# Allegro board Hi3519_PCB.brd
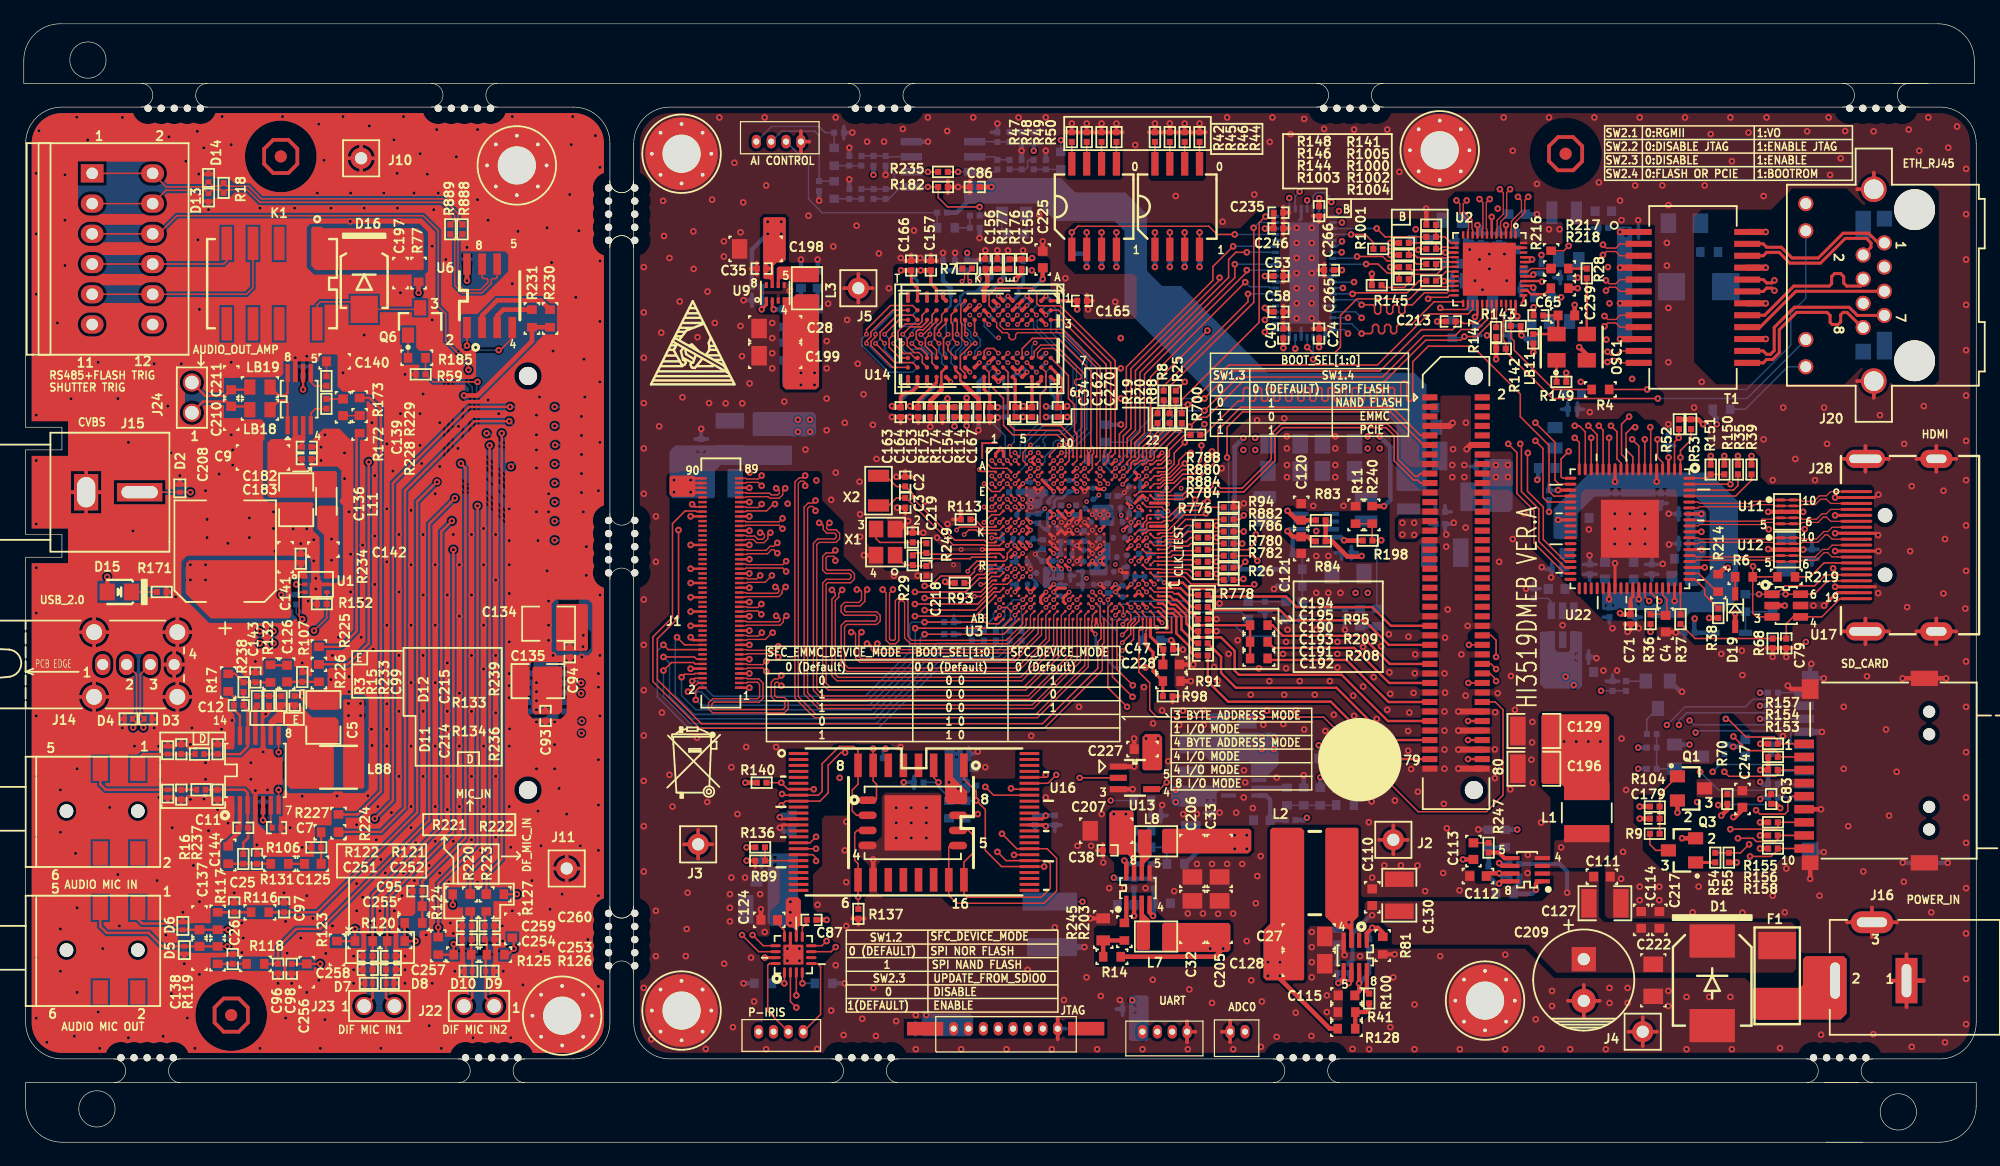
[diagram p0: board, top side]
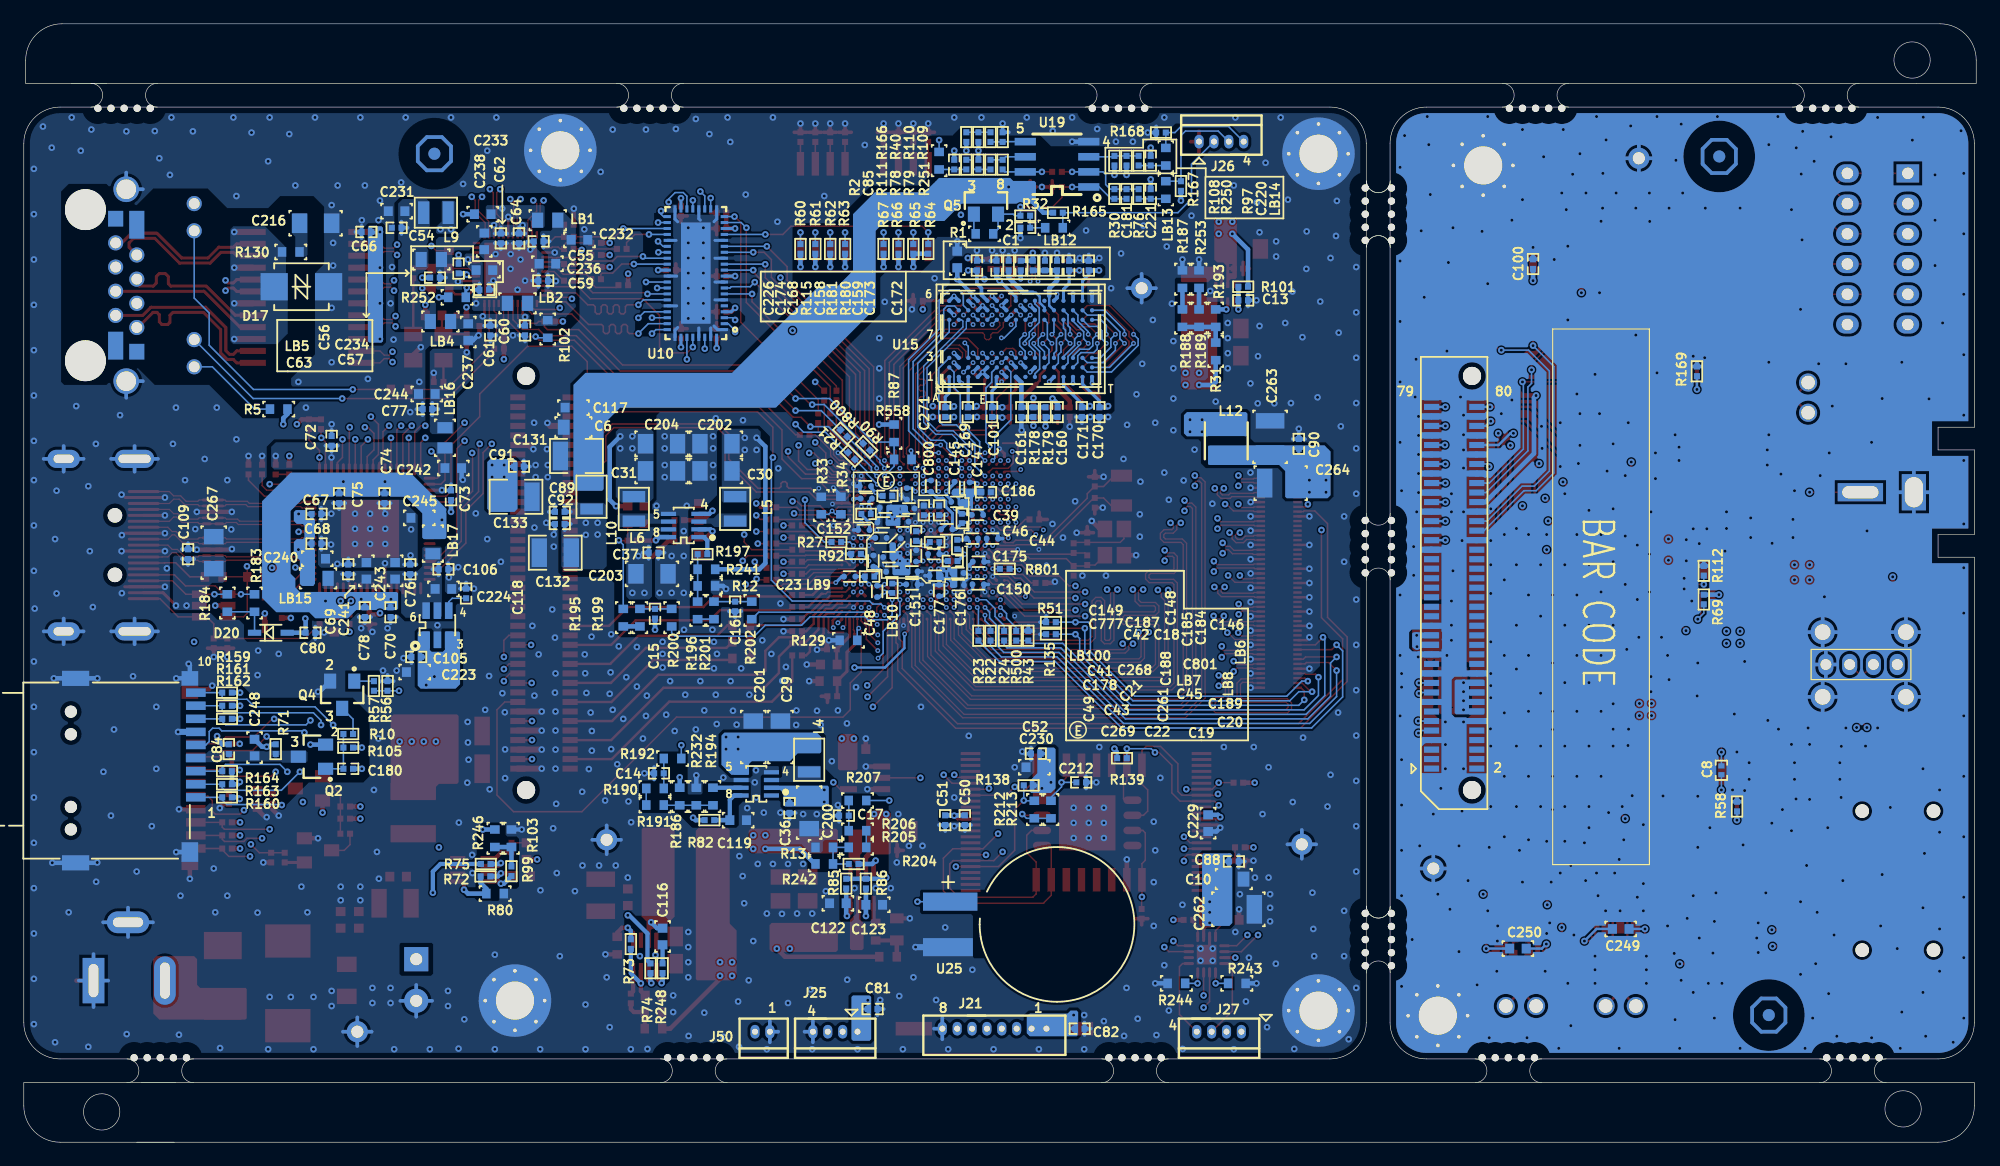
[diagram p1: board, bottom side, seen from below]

Outline 164.07 x 93.99 mm; copper layers: TOP, GND02, ART03, ART04, POWER5, BOTTOM. Coordinates in mm from the lower left corner of the outline.
Outline path: circle c5.39,90.95 r1.52 ; circle c6.15,2.8 r1.52 ; circle c157.53,2.55 r1.52 ; 154.21,5 0.16,5 0.16,3.05 arc(1.05,0.89) 3.21,0 154.59,0 ; 49.24,75.19 arc(50.24,76.19) 51.24,75.19 ; 51.24,80.79 arc(50.24,79.79) 49.24,80.79 ; 51.24,19.83 arc(50.24,18.83) 49.24,19.83 ; 151.29,5 164.07,5 164.07,3.05 arc(163.18,0.89) 161.03,0 151.41,0 ; 157.13,88.99 163.92,88.99 163.92,90.94 arc(163.02,93.1) 160.87,93.99 3.05,93.99 arc(0.89,93.1) 0,90.94 0,88.99 160.05,88.99 ; 0.16,83.94 0.16,60.09 3.21,60.09 3.21,58.18 0.16,58.18 0.16,51.07 3.21,51.07 3.21,49.16 0.16,49.16 0.16,10.05 arc(1.05,7.89) 3.21,7 46.21,7 arc(48.36,7.89) 49.26,10.05 49.26,83.94 arc(48.36,86.1) 46.21,86.99 3.21,86.99 arc(1.05,86.1) 0.16,83.94 ; 51.26,83.94 51.26,10.05 arc(52.15,7.89) 54.31,7 161.03,7 arc(163.18,7.89) 164.07,10.05 164.07,83.94 arc(163.18,86.1) 161.03,86.99 54.31,86.99 arc(52.15,86.1) 51.26,83.94

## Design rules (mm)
net group $5N25: nets $5N25 $5N30
net group $5N37: nets $5N37 $5N91
net group $5N94: nets $5N94 $5N95
net group $5N162: nets $5N55 $5N162
net group $12N181: nets $12N181 RGMII_TX_CLK/VO_DE
net group $12N307: nets $12N307 NF_DQ1/SFC_CLK
net group $12N323: nets $12N323 RGMII_TXD0/VO_DATA10
net group $12N325: nets $12N325 RGMII_TXD1/VO_VS
net group $12N327: nets $12N327 RGMII_TXD2/VO_DATA9
net group $12N329: nets $12N329 RGMII_TXD3/VO_HS
net group $12N331: nets $12N331 RGMII_TX_EN
net group $12N369: nets $12N369 MDCK
net group $12N378: nets $12N378 EPHY_CLK/VO_DATA8
net group $13N13: nets $13N13 SENSOR_CLK
net group $13N35: nets $13N35 VO_CLK
net group $13N216: nets $13N216 SENSOR_HS
net group $13N220: nets $13N220 SENSOR_VS
net group $14N244: nets $14N244 AC_MICIN0_L/DIFFIN0_P
net group $14N249: nets $14N249 AC_MICIN0_R/DIFFIN0_N
net group $14N260: nets $14N260 AC_IN1_P
net group $14N261: nets $14N261 AC_IN1_N
net group $15N332: nets $15N332 SYS_RSTN_OUT
net group $16N153: nets $16N153 REG_OUT_1.05V
net group $16N389: nets $16N389 LED1_LINK/PHY_AD1
net group $16N414: nets $16N414 EPHY_CLK
net group $16N440: nets $16N440 $16N442
net group $16N505: nets $16N505 RGMII_RX_CLK
net group $17N661: nets $17N661 HOT_PLUG_SII9022A
net group $17N672: nets $17N672 PER_RSTN
net group $18N447: nets $18N447 CEC_A_SII9022A
net group $20N434: nets $20N434 $20N437
net group $20N436: nets $20N436 SDIO1_CARD_POWER_EN
net group $20N553: nets $20N553 $20N555
net group $20N554: nets $20N554 SDIO0_CARD_POWER_EN
net group $21N204: nets $21N204 $21N213
net group $21N216: nets $21N216 $21N220
net group $26N69: nets $26N69 $26N71
net group $27N24: nets $27N24 $27N32
net group $28N1280: nets $28N1280 FLASH_TRIG_C
net group AC_OUTR_C: nets AC_OUTR_C AC_OUTR_PAM8303D
net group AN0: nets AN0 RGMII_RXD2/AN0
net group AN1: nets AN1 RGMII_RXD3/AN1
net group DDR3_DQS0_P: nets DDR3_DQS0_N DDR3_DQS0_P
net group DDR3_DQS1_N: nets DDR3_DQS1_N DDR3_DQS1_P
net group DDR3_DQS2_N: nets DDR3_DQS2_N DDR3_DQS2_P
net group DDR3_DQS3_N: nets DDR3_DQS3_N DDR3_DQS3_P
net group HDMI_TX0: nets TX0+_SII9022A TX0-_SII9022A
net group HDMI_TX1: nets TX1+_SII9022A TX1-_SII9022A
net group HDMI_TX2: nets TX2+_SII9022A TX2-_SII9022A
net group HDMI_TXC: nets TXC+_SII9022A TXC-_SII9022A
net group PHY_AD2: nets PHY_AD2 RGMII_RX_DV/PHY_AD2
net group RGMII_RXD0/SELRGV: nets RGMII_RXD0/SELRGV SELRGV
net group RGMII_RXD1/TXDLY: nets RGMII_RXD1/TXDLY TXDLY
net group USB2_DM_C: nets USB2_DM_C USB2_DP_C
net group USB2_DP: nets USB2_DM USB2_DP
net group $5N45: nets $5N45 $5N49 $5N52
net group $5N171: nets $5N85 $5N86 $5N88 $5N171 DRIVE+ IRIS_5V0
net group $6N109: nets 0.9V_VDD_MEDIA $6N85 $6N109 $6N179 $6N199 MP2143_FB SVB_PWM_MEDIA
net group $6N194: nets $6N42 $6N47 $6N194
net group $7N111: nets 0.9V_VDD_CPU $7N68 $7N92 $7N111 $7N113 $7N170 SVB_PWM_CPU
net group $7N137: nets $7N137 $7N148 $7N150 $7N173 $7N232 SVB_PWM_DDR
net group $8N176: nets 0.9V_VDD $8N27 $8N29 $8N46 $8N94 $8N176 SVB_PWM_VDD
net group $12N11: nets $12N8 $12N11 $12N13
net group $13N249: nets $8N21 $8N88 $8N96 $13N249 SPI0_CSN SPI0_MOSI/I2C0_SDA SPI0_SCLK/I2C0_SCL
net group $18N493: nets $18N493 TX_DSCL_SII9022A TX_DSDA_SII9022A
net group $21N200: nets $21N200 $21N201 $21N203 $21N217 $21N227 $21N229 $21N230 DC_IRIS_PWM DRIVING+_G
net group $25N49: nets $25N49 $25N63 AC_IN0_N_C AC_INO_P_C AC_MICBIAS0_DIF_C
net group $25N107: nets $25N107 AC_IN0L_C AC_MICBIAS0_L_C AC_MICIN0_L/DIFFIN0_P_C
net group $25N123: nets $25N123 AC_IN0R_C AC_MICBIAS0_R_C AC_MICIN0_R/DIFFIN0_N_C
net group $25N140: nets $25N140 $25N160 AC_IN1_N_C AC_IN1_P_C AC_MICBIAS1_C
net group $26N28: nets $26N28 $26N31 $26N33 $26N37 AC_OUTR_SGM8903 SGM8903_OUTR
net group $26N114: nets $26N114 $26N116 $26N122 $26N127 AC_OUTL_SGM8903 SGM8903_OUTL
net group $26N154: nets 5V0_C 5V_AUDIO 5V_C_AUDIO $26N154 $26N162
net group $27N23: nets $27N23 $27N30 AC_OUTL/AC_OUTR AC_OUTL_C AC_OUTL_PAM8303D
net group $28N947: nets $28N947 $28N948 UART1_RTSN_C
net group $28N1296: nets 3V3_C $28N1296 USB2_OVRCUR_C
net group $28N1347: nets $28N945 $28N1347 RS485_A_D+ RS485_B_D-
net group AC_MICBIAS0: nets AC_MICBIAS0 AC_MICBIAS0_L AC_MICBIAS0_R
net group DDR: nets DDR3_A0 DDR3_A1 DDR3_A2 DDR3_A3 DDR3_A4 DDR3_A5 DDR3_A6 DDR3_A7 DDR3_A8 DDR3_A9 DDR3_A10 DDR3_A11 DDR3_A12 DDR3_A13 DDR3_A14 DDR3_A15 DDR3_BA0 DDR3_BA1 DDR3_BA2 DDR3_CAS_N DDR3_CKE DDR3_CS_N DDR3_DM0 DDR3_DM1 DDR3_DM2 DDR3_DM3 DDR3_DQ0 DDR3_DQ1 DDR3_DQ2 DDR3_DQ3 DDR3_DQ4 DDR3_DQ6 DDR3_DQ7 DDR3_DQ8 DDR3_DQ9 DDR3_DQ10 DDR3_DQ11 DDR3_DQ12 DDR3_DQ13 DDR3_DQ14 DDR3_DQ15 DDR3_DQ16 DDR3_DQ17 DDR3_DQ18 DDR3_DQ19 DDR3_DQ20 DDR3_DQ21 DDR3_DQ22 DDR3_DQ23 DDR3_DQ24 DDR3_DQ25 DDR3_DQ26 DDR3_DQ27 DDR3_DQ28 DDR3_DQ29 DDR3_DQ30 DDR3_DQ31 DDR3_ODT DDR3_RAS_N DDR3_RESET_N DDR3_WE_N
net group MDI: nets MDIN0 MDIN1 MDIN2 MDIN3 MDIP0 MDIP1 MDIP2 MDIP3
net group MIPI_CLK: nets MIPI0_CKP MIPI1_CKM MIPI1_CKP MIPI2_CKM MIPI2_CKP
net group MIPI_DATA: nets MIPI0_D0M MIPI0_D0P MIPI0_D1M MIPI0_D1P MIPI0_D2M MIPI0_D2P MIPI0_D3M MIPI0_D3P MIPI1_D0M MIPI1_D0P MIPI1_D1M MIPI1_D1P MIPI1_D2M MIPI1_D2P MIPI1_D3M MIPI1_D3P MIPI2_D0M MIPI2_D0P MIPI2_D2M MIPI2_D2P MIPI2_D3M MIPI2_D3P
net group MX: nets MX0+ MX0- MX1+ MX1- MX2+ MX2- MX3+ MX3-
nets with their own width: min track width 0.254; nets 1.8V 1V2A_SII9022A 1V2D_SII9022A 3V3 DDRIO_1.5V/1.35V DVDD_1.05V GND IO3V3_SII9022A
nets with their own width: min track width 0.381; nets AGND

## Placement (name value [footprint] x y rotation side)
C1  5.6PF  [SC0402]  79.91 76.85 0 bottom
C2  20PF  [SC0402]  74.07 55.51 90 top
C3  20PF  [SC0402]  74.07 53.74 270 top
C4  1NF  [SC0603]  137.97 43.58 270 top
C5  22UF  [SC1210B]  25.18 35.7 90 top
C6  10UF  [SC0805]  117.89 60.09 0 bottom
C7  330N  [HSC0402-TA]  21.24 26.43 180 top
C8  330N  [HSC0402-TA]  21.41 31.26 90 bottom
C9  10UF  [SC1206]  20.1 57.55 180 top
C10  10UF  [SC0805]  62.39 22.11 180 bottom
C11  47PF  [SC0402]  18.45 26.42 0 top
C12  47PF  [SC0402]  18.06 36.72 180 top
C13  2.2UF  [HSC0402]  61.6 70.75 180 bottom
C14  2.2UF  [HSC0402]  110.7 31 0 bottom
C15  2.2UF  [SC0402]  111.03 44.41 270 bottom
C16  2.2UF  [SC0402]  104.3 45.02 270 bottom
C17  2.2UF  [SC0402]  95.15 27.45 0 bottom
C18  2.2UF  [SC0402-BGA]  89.69 53.26 180 bottom
C19  2.2UF  [SC0402-BGA]  87.48 47.61 0 bottom
C20  2.2UF  [SC0402-BGA]  85.58 47.84 180 bottom
C21  2.2UF  [SC0402-BGA]  90.72 50.41 135 bottom
C22  2.2UF  [SC0402-BGA]  89.44 47.97 180 bottom
C23  2.2UF  [SC0402-BGA]  94.67 47.54 180 bottom
C24  100NF  [SC0402]  108.85 67.96 90 top
C25  2.2UF  [HSC0402]  17.68 19.73 90 top
C26  2.2UF  [HSC0402]  17.56 15.39 90 top
C27  22UF  [SC1206]  107.98 17.29 0 top
C28  22UF  [SC1206]  63.14 68.38 180 top
C29  22UF  [SC1206]  100.49 34.05 90 bottom
C30  22UF  [SC1206]  105.91 56.41 0 bottom
C31  22UF  [SC1206]  110.48 56.41 180 bottom
C32  22UF  [SC1206]  98.2 18.94 90 top
C33  22UF  [SC1206]  100.49 23.64 270 top
C34  1UF  [SC0402]  83.32 61.36 270 top
C35  100NF  [SC0402]  62.01 73.42 180 top
C36  100NF  [SC0402]  99.73 28.08 270 bottom
C37  100NF  [SC0402]  111.16 49.54 180 bottom
C38  100NF  [SC0402]  91.09 24.53 180 top
C39  2.2UF  [SC0402-BGA]  83.93 52.72 180 bottom
C40  100NF  [SC0402]  105.85 67.96 90 top
C41  100NF  [SC0402-BGA]  91.86 52.08 0 bottom
C42  100NF  [SC0402-BGA]  91.67 53.33 0 bottom
C43  100NF  [SC0402-BGA]  91.38 49.16 0 bottom
C44  100NF  [SC0402-BGA]  82.68 50.73 180 bottom
C45  100NF  [SC0402-BGA]  87.61 49.43 0 bottom
C46  100NF  [SC0402-BGA]  84.36 50.73 180 bottom
C47  100NF  [SC0402]  96.17 41.42 0 top
C48  100NF  [SC0402-BGA]  92.36 46.29 90 bottom
C49  100NF  [SC0402-BGA]  92.67 48.84 90 bottom
C50  100NF  [SC0402]  84.99 27.07 270 bottom
C51  100NF  [SC0402]  86.64 27.07 270 bottom
C52  100NF  [SC0402]  79.02 32.65 0 bottom
C53  100NF  [SC0402]  105.44 72.79 0 top
C54  100NF  [SC0402]  132.75 76.85 0 bottom
C55  100NF  [SC0402]  120.81 75.71 0 bottom
C56  100NF  [SC0402]  127.54 73.42 90 bottom
C57  100NF  [SC0402]  125.38 71.64 180 bottom
C58  100NF  [SC0402]  105.44 69.79 0 top
C59  100NF  [SC0402]  120.43 72.4 0 bottom
C60  100NF  [SC0402]  121.95 68.21 270 bottom
C61  100NF  [SC0402]  124.87 68.21 270 bottom
C62  100NF  [SC0402]  123.98 75.96 270 bottom
C63  100NF  [SC0402]  129.52 72.66 0 bottom
C64  100NF  [SC0402]  122.46 75.96 270 bottom
C65  100NF  [SC0402]  127.28 69.48 180 top
C66  100NF  [SC0402]  135.29 76.5 0 bottom
C67  100NF  [SC0402]  139.48 52.8 180 bottom
C68  100NF  [SC0402]  139.48 50.31 180 bottom
C69  100NF  [SC0402]  136.81 48.15 90 bottom
C70  100NF  [SC0402]  133.25 44.54 270 bottom
C71  100NF  [SC0402]  135.03 43.96 270 top
C72  100NF  [SC0402]  138.21 58.94 90 bottom
C73  100NF  [SC0402]  128.17 54.37 270 bottom
C74  100NF  [SC0402]  133.76 54.12 270 bottom
C75  100NF  [SC0402]  137.57 54.12 270 bottom
C76  100NF  [SC0402]  131.6 48.15 90 bottom
C77  100NF  [SC0402]  130.15 61.61 0 bottom
C78  100NF  [SC0402]  135.41 44.54 270 bottom
C79  100NF  [SC0402]  148.11 41.92 90 top
C80  100NF  [SC0402]  139.98 42.81 180 bottom
C81  100NF  [SC0402]  92.74 11.19 180 bottom
C82  100NF  [SC0402]  75.34 9.54 180 bottom
C83  100NF  [SC0402]  146.84 28.84 270 top
C84  100NF  [SC0402]  146.84 33.03 90 bottom
C85  100NF  [SC0402]  85.88 82.16 90 bottom
C86  100NF  [SC0402]  79.91 80.28 180 top
C87  100NF  [SC0402]  66.2 18.68 0 top
C88  100NF  [SC0402]  62.38 23.6 180 bottom
C89  100NF  [SC0402]  119.03 52.97 0 bottom
C90  100NF  [SC0402]  56.93 58.69 90 bottom
C91  100NF  [SC0402]  122.46 56.78 180 bottom
C92  100NF  [SC0402]  119.03 51.96 0 bottom
C93  100NF  [SC0402]  43.85 35.83 270 top
C94  100NF  [SC0402]  45.88 41.16 270 top
C95  100NF  [SC0402]  33.08 21.1 180 top
C96  100NF  [SC0402]  21.37 14.58 270 top
C97  100NF  [SC0402]  21.87 19.73 90 top
C98  100NF  [SC0402]  22.51 14.58 270 top
C99  100NF  [SC0402]  22.76 37.1 90 top
C100  100NF  [SC0402]  37.24 73.8 90 bottom
C101  1UF  [SC0402]  82.71 61.36 270 bottom
C105  100NF  [SC0402]  131.09 40.78 0 bottom
C106  100NF  [SC0402]  128.81 48.15 180 bottom
C109  100NF  [SC0402]  150.27 49.42 90 bottom
C110  100NF  [SC0603]  113.31 20.59 90 top
C111  100NF  [SC0603]  132.62 22.32 0 top
C112  100NF  [SC0603]  122.2 22.37 180 top
C113  100NF  [SC0603]  121.82 24.46 270 top
C114  100NF  [SC0603]  135.92 18.68 90 top
C115  100NF  [SC0603]  111.16 12.33 180 top
C116  100NF  [SC0603]  110.39 17.29 90 bottom
C117  100NF  [SC0603]  117.89 61.74 0 bottom
C118  10NF  [SC0402]  126.9 46.12 90 bottom
C119  2.2UF  [SC0603]  104.04 27.07 180 bottom
C120  2.2UF  [SC0603]  107.35 52.97 90 top
C121  2.2UF  [SC0603]  107.35 50.18 270 top
C122  2.2UF  [SC0603]  95.66 20.08 0 bottom
C123  2.2UF/NC  [SC0603]  92.61 19.95 180 bottom
C124  2.2UF  [SC0603]  62.64 18.68 0 top
C125  2.2UF  [SC0603]  24.29 23.4 180 top
C126  2.2UF  [SC0603]  22.13 39.38 270 top
C127  22UF  [SC1210B]  132.87 20.08 0 top
C128  22UF  [SC1206]  107.98 15 0 top
C129  22UF  [SC1210B]  126.9 34.56 180 top
C130  22UF  [SC1210B]  115.59 20.76 90 top
C131  22UF  [SC1210B]  117.63 57.67 0 bottom
C132  22UF  [SC1210B]  119.41 49.54 0 bottom
C133  22UF  [SC1210B]  122.71 54.24 180 bottom
C134  22UF  [SC1210B]  44.1 43.58 180 top
C135  22UF  [SC1210B]  43.21 38.75 180 top
C136  22UF  [SC1210B]  22.89 53.99 270 top
C137  15PF  [SC0603]  14.76 18.55 90 top
C138  15PF  [SC0603]  14.76 15.76 270 top
C139  1UF  [SC0603]  26.83 61.76 90 top
C140  1UF  [SC0603]  26.13 65.62 180 top
C141  100NF  [SC0603]  22 49.16 90 top
C142  100NF  [SC0603]  25.18 49.8 180 top
C143  680PF  [SC0402]  19.46 39.05 90 top
C144  680PF  [SC0402]  19.59 23.81 90 top
C145  1UF  [SC0402-BGA]  85.86 55.03 90 bottom
C146  1UF  [SC0402-BGA]  85.66 53.81 0 bottom
C147  1UF  [SC0402-BGA]  84.59 54.98 90 bottom
C148  1UF  [SC0402-BGA]  89.87 54.5 270 bottom
C149  1UF  [SC0402-BGA]  93.35 55.13 0 bottom
C150  1UF  [SC0402-BGA]  83.88 46.88 180 bottom
C151  1UF  [SC0402-BGA]  89.44 46.88 180 bottom
C152  1UF  [SC0402-BGA]  93.48 51.45 0 bottom
C153  1UF  [SC0402]  76.18 61.36 270 top
C154  1UF  [SC0402]  79.23 61.36 90 top
C155  1UF  [SC0402]  83.85 73.8 270 top
C156  1UF  [SC0402]  80.8 73.8 90 top
C157  1UF  [SC0402]  76.23 73.67 90 top
C158  1UF  [SC0402]  80.29 73.67 270 bottom
C159  1UF  [SC0402]  77.25 73.67 90 bottom
C160  1UF  [SC0402]  77.2 61.36 90 bottom
C161  1UF  [SC0402]  80.24 61.36 270 bottom
C162  1UF  [SC0402]  84.74 61.36 270 top
C163  1UF  [SC0402]  73.69 61.36 270 top
C164  1UF  [SC0402]  75.16 61.36 270 top
C165  1UF  [SC0402]  88.93 70.71 0 top
C166  1UF  [SC0402]  74.58 73.67 90 top
C167  1UF  [SC0402]  81.18 61.36 270 top
C168  1UF  [SC0402]  82.33 73.67 90 bottom
C169  1UF  [SC0402]  84.74 61.36 270 bottom
C170  1UF  [SC0402]  73.69 61.36 270 bottom
C171  1UF  [SC0402]  75.16 61.36 270 bottom
C172  1UF  [SC0402]  74.58 73.67 90 bottom
C173  1UF  [SC0402]  76.23 73.67 90 bottom
C174  1UF  [SC0402]  83.98 73.67 90 bottom
C175  1UF  [SC0402-BGA]  83.85 48.78 180 bottom
C176  2.2UF  [SC0402-BGA]  85.54 46.82 180 bottom
C177  1UF  [SC0402-BGA]  87.15 46.37 90 bottom
C178  1UF  [SC0402-BGA]  92.04 50.79 180 bottom
C179  1UF  [SC0402]  137.06 27.19 0 top
C180  1UF  [SC0402]  136.81 31.38 0 bottom
C181  1UF  [SC0402]  71.4 79.69 270 bottom
C182  1UF  [SC0402]  23.78 58.43 0 top
C183  1UF  [SC0402]  23.78 57.42 0 top
C184  4.7UF  [SC0402]  87.15 53.1 90 bottom
C185  4.7UF  [SC0402]  88.44 53.1 90 bottom
C186  4.7UF  [SC0402]  83.22 54.62 180 bottom
C187  4.7UF  [SC0402]  91.5 54.32 180 bottom
C188  4.7UF  [SC0402]  89.08 50.94 90 bottom
C189  4.7UF  [SC0402]  86.01 48.85 0 bottom
C190  4.7UF  [SC0402]  99.09 43.96 180 top
C191  4.7UF  [SC0402]  99.09 41.92 180 top
C192  4.7UF  [SC0402]  99.09 40.91 180 top
C193  4.7UF  [SC0402]  99.09 42.94 180 top
C194  4.7UF  [SC0402]  99.09 45.99 180 top
C195  4.7UF  [SC0402]  99.09 44.97 180 top
C196  22UF  [SC1210B]  126.9 31.38 180 top
C197  1UF  [SC0603]  31.65 73.04 270 top
C198  22UF  [SC1206]  61.5 75.07 180 top
C199  22UF  [SC1206]  63.14 66.1 180 top
C200  22UF  [SC1206]  98.07 27.7 270 bottom
C201  22UF  [SC1206]  102.77 34.05 90 bottom
C202  22UF  [SC1206]  105.91 58.7 0 bottom
C203  22UF  [SC1206]  111.28 47.77 180 bottom
C204  22UF  [SC1206]  110.48 58.7 180 bottom
C205  22UF  [SC1206]  100.49 18.94 90 top
C206  22UF  [SC1206]  98.2 23.64 270 top
C207  22UF  [SC1206]  90.96 26.18 180 top
C208  220UF  [SCAPC2-280-327]  16.92 49.67 90 top
C209  220UF  [CAPC2-138-335]  131.09 15.38 270 top
C210  220PF  [SC0603]  17.43 61.14 270 top
C211  220PF  [SC0603]  17.43 63.93 90 top
C212  1NF  [SC0402]  75.21 30.24 0 bottom
C213  1NF  [SC0402]  119.92 68.98 180 top
C214  1NF  [SC0402]  13.24 29.22 270 top
C215  1NF  [SC0402]  13.24 33.03 90 top
C216  1NF  [SC1206]  139.55 77.23 180 bottom
C217  1NF  [SC0603]  137.44 18.68 90 top
C218  15PF  [SC0402]  75.85 48.02 270 top
C219  15PF  [SC0402]  74.71 50.81 90 top
C220  15PF  [SC0402]  69.37 82.49 90 bottom
C221  15PF  [SC0402]  69.37 79.69 90 bottom
C222  10UF  [SC1206C]  136.94 13.6 270 top
C223  10UF  [SC0603]  131.22 39.51 0 bottom
C224  10UF  [SC0603]  128.81 46.5 180 bottom
C225  10UF  [SC0603]  85.63 74.18 90 top
C226  10UF  [SC0603]  85.63 74.18 90 bottom
C227  10UF  [SC0603]  94.01 33.03 180 top
C228  10UF  [SC0603]  96.42 40.15 0 top
C229  10UF  [SC0603]  64.55 26.81 270 bottom
C230  10UF  [SC0603]  79.15 31.51 0 bottom
C231  10UF  [SC0603]  132.75 78.25 0 bottom
C232  10UF  [SC0603]  117.38 75.83 180 bottom
C233  10UF  [SC0603]  125.51 77.99 0 bottom
C234  10UF  [SC0603]  125.37 73.29 180 bottom
C235  100NF  [SC0402]  105.44 78.12 0 top
C236  10UF  [SC0603]  120.07 73.83 0 bottom
C237  10UF  [SC0603]  126.73 68.09 270 bottom
C238  10UF  [SC0603]  125.38 75.71 270 bottom
C239  10UF  [SC0603]  129.63 69.48 0 top
C240  10UF  [SC0603]  139.42 49.04 180 bottom
C241  10UF  [SC0603]  135.29 48.02 90 bottom
C242  10UF  [SC0603]  127.98 56.66 180 bottom
C243  10UF  [SC0603]  132.87 48.02 90 bottom
C244  10UF  [SC0603]  130.21 62.88 0 bottom
C245  10UF  [SC0603]  130.84 52.47 0 bottom
C246  100NF  [SC0402]  105.44 76.79 0 top
C247  10UF  [SC0603]  144.43 28.84 270 top
C248  10UF  [SC0603]  144.68 33.16 90 bottom
C249  10UF  [SC0603]  29.88 17.92 180 bottom
C250  10UF  [SC0603]  38.51 16.27 0 bottom
C251  33PF  [SC0402]  28.91 15.64 180 top
C252  33PF  [SC0402]  30.85 15.64 0 top
C253  33PF  [SC0402]  39.15 17.03 0 top
C254  33PF  [SC0402]  37.24 17.03 180 top
C255  4.7UF  [SC0603]  32.78 19.83 180 top
C256  4.7UF  [SC0603]  23.78 14.29 270 top
C257  10PF  [SC0402]  30.85 14.49 0 top
C258  10PF  [SC0402]  28.91 14.49 180 top
C259  10PF  [SC0402]  37.24 18.18 180 top
C260  10PF  [SC0402]  39.15 18.18 0 top
C261  470NF  [SC0402-BGA]  89.09 49.27 90 bottom
C262  100UF  [SC1210]  62.01 19.57 180 bottom
C263  100UF  [SC1210]  59.34 59.28 90 bottom
C264  100UF  [SC1210]  58.45 55.39 0 bottom
C265  100NF  [SC0402]  109.68 73.29 180 top
C266  100NF  [SC0402]  108.85 78.25 270 top
C267  10UF  [SC1206]  148.11 49.54 90 bottom
C268  100NF  [SC0402-BGA]  90.2 52.16 180 bottom
C269  100NF  [SC0402-BGA]  91.13 47.94 0 bottom
C270  1UF  [SC0402]  86.9 61.36 270 top
C271  1UF  [SC0402]  86.64 61.36 270 bottom
C777  100NF  [SC0402-BGA]  93.27 54.09 0 bottom
C800  100NF  [SC0402-BGA]  87.83 55.14 90 bottom
C801  100NF  [SC0402-BGA]  86.51 51.51 0 bottom
D1  DZ  [SD2723]  141.89 13.35 90 top
D2  ESD8V0R1B_02LRH  [HSOD882]  13.11 54.95 90 top
D3  ESD8V0R1B_02LRH  [HSOD882]  10.44 35.57 0 top
D4  ESD8V0R1B_02LRH  [HSOD882]  8.79 35.57 180 top
D5  PESD5V0S1BL315  [HSOD882]  13.49 16.14 270 top
D6  PESD5V0S1BL315  [HSOD882]  13.37 18.18 90 top
D7  PESD5V0S1BL315  [HSOD882]  28.99 13.35 180 top
D8  PESD5V0S1BL315  [HSOD882]  30.76 13.35 0 top
D9  PESD5V0S1BL315  [HSOD882]  39.15 14.37 0 top
D10  PESD5V0S1BL315  [HSOD882]  37.37 14.37 180 top
D11  PESD5V0S1BL315  [HSOD882]  12.1 29.3 270 top
D12  PESD5V0S1BL315  [HSOD882]  12.1 32.94 90 top
D13  PESD5V0S1BL315  [HSOD882]  15.52 79.39 270 top
D14  PESD5V0S1BL315  [HSOD882]  15.52 81.04 270 top
D15  -  [SD0805-LED]  8.03 46.24 0 top
D16  D  [SD1714A]  28.61 72.28 90 top
D17  TISP4350H3BJR_S  [SD1714D]  140.75 71.9 180 bottom
D19  D_A  [HSOD323A]  143.82 44.72 90 top
D20  D_A  [HSOD323A]  143.31 42.81 0 bottom
F1  0451005MRL  [SF6127]  147.35 13.98 90 top
J1  MIPI_90_CON_F  [SED90-F-A]  58.58 47 90 top
J2  TSW_101_23_F_S  [HEAD0101-T-B]  115.09 25.41 0 top
J3  TSW_101_23_F_S  [HEAD0101-T-B]  56.67 25.03 0 top
J4  TSW_101_23_F_S  [HEAD0101-T-B]  136.05 9.29 0 top
J5  TSW_101_23_F_S  [HEAD0101-T-B]  70.13 71.77 0 top
J10  TSW_101_23_F_S  [HEAD0101-T-B]  28.35 82.69 0 top
J11  TSW_101_23_F_S  [HEAD0101-T-B]  45.62 23 0 top
J12  475792245  [TF_CARD-MISOSD]  157.12 31.23 90 top
J13  475792245  [TF_CARD-MISOSD]  157.12 31.23 270 bottom
J14  UB31123_K1_4F  [USB4-200-1907]  6.63 40.15 0 top
J15  AV_84_5Y_HW  [VAF2]  5.24 54.62 270 top
J16  DC-005-B  [PWC0103-M-N]  158.22 13.58 0 top
J17  HEAD6_ALARM  [J6-W2_54MM-141R]  8.29 75.07 270 top
J18  80PIN-CON  [CONN80-0_8MM-ERF8-DV]  120.36 47 90 top
J19  80PIN-CON  [CONN80-0_8MM-ERM8-DV]  43.87 47 270 bottom
J20  E5J88_14LJ24_L  [MJ8-SRLFY]  156.36 75.58 270 top
J21  SDW12501A_8A_HW  [WBC0108-49T]  78.14 9.54 0 bottom
J22  TSW_102_23_F_S  [SIP-2P]  38.26 11.44 180 top
J23  TSW_102_23_F_S  [SIP-2P]  29.88 11.44 0 top
J24  TSW_102_23_F_S  [SIP-2P]  14.13 62.58 90 top
J25  SDW12501_4A_HW  [WBC0104-49T]  94.01 9.29 0 bottom
J26  SDW12501_4A_HW  [WBC0104-49T]  65.31 84.09 180 bottom
J27  SDW12501_4A_HW  [WBC0104-49T]  61.75 9.29 0 bottom
J28  HDMI  [MOLEX_47151]  158.51 50.18 90 top
J29  AUDIO  [PHONEJ6]  6.13 16.14 0 top
J30  AUDIO  [PHONEJ6]  6.13 27.83 0 top
J50  TJC3_2A_34HW  [SIP-2P-20]  101.38 9.29 0 bottom
K1  UD2_3NU_L5  [SRLY8-87-283]  20.86 72.15 180 top
L1  3.9UH  [SPL0404L]  131.35 27.7 90 top
L2  4.7UH  [SL2828]  108.49 22.62 90 top
L3  2.2UH  [HSL1008]  65.82 71.77 270 top
L4  1U  [HSL1008]  98.07 32.15 90 bottom
L5  2.2UH  [HSL1008]  104.3 53.23 270 bottom
L6  2.2UH  [HSL1008]  112.81 53.23 270 bottom
L7  2.2UH  [HSL1008]  95.15 17.29 180 top
L8  2.2UH  [HSL1008]  95.15 25.29 180 top
L9  2.2UH  [HSL1008]  129.44 78.12 0 bottom
L10  2.2UH  [HSL1008]  116.36 54.24 90 bottom
L11  100NH  [SL0805B]  25.43 53.86 90 top
L12  4.7U  [SPL0303A]  63.02 58.94 90 bottom
L88  4.7U  [SPL0303A]  26.45 31.51 180 top
LB1  LFBK2125HS101_T  [SL0805]  120.05 77.48 0 bottom
LB2  LFBK2125HS101_T  [SL0805]  122.59 70.5 0 bottom
LB4  LFBK2125HS101_T  [SL0805]  129.06 68.98 180 bottom
LB5  LFBK2125HS101_T  [SL0805]  129.82 74.18 180 bottom
LB6  BLM15HG102SN1D  [SL0402]  85.25 52.42 270 bottom
LB7  BLM15HG102SN1D  [SL0402]  87.53 50.43 0 bottom
LB8  BLM15HG102SN1D  [SL0402]  85.63 50.23 270 bottom
LB9  BLM15HG102SN1D  [SL0402]  92.99 47.54 0 bottom
LB10  BLM15HG102SN1D  [SL0402]  91.09 46.56 90 bottom
LB11  BLM15HG102SN1D  [SL0402]  126.85 67.52 90 top
LB12  MGLB1608_030T_LF  [SL0603]  77.5 76.85 180 bottom
LB13  MGLB1608_030T_LF  [SL0603]  68.1 80.02 90 bottom
LB14  MGLB1608_030T_LF  [SL0603]  68.1 82.82 90 bottom
LB15  MGLB2012_220T_LF  [SL0805]  139.35 47.39 0 bottom
LB16  MGLB2012_220T_LF  [SL0805]  128.68 59.2 270 bottom
LB17  MGLB2012_220T_LF  [SL0805]  129.7 50.31 90 bottom
LB18  MGLB2012_220T_LF  [SL0805]  19.84 61.56 180 top
LB19  MGLB2012_220T_LF  [SL0805]  19.84 63.46 180 top
LB100  BLM15HG102SN1D  [SL0402]  93.29 52.8 0 bottom
M1  HOLE  [MTH_C6MMD3P2MM]  118.99 83.36 0 top
M2  HOLE  [MTH_C6MMD3P2MM]  55.28 11.06 0 top
M3  HOLE  [MTH_C6MMD3P2MM]  55.28 83.07 0 top
M4  HOLE  [MTH_C6MMD3P2MM]  122.8 11.9 0 top
M5  HOLE  [MTH_C6MMD3P2MM]  41.43 82.09 0 top
M6  HOLE  [MTH_C6MMD3P2MM]  45.24 10.63 0 top
NOREF  -  []  0.16 10.05 0 top
NOREF#2  -  []  58.83 32.02 0 top
NOREF#3  -  []  78.75 72.32 0 top
NOREF#4  -  []  132.47 194.3 0 top
NOREF#5  -  [unnamed#2]  10.36 6 0 top
NOREF#6  -  [unnamed#2]  70.69 6 0 top
NOREF#7  -  [unnamed#2]  39.32 6 0 top
NOREF#8  -  []  4.48 0 90 top
NOREF#9  -  [unnamed#2]  37.03 87.99 180 top
NOREF#10  -  []  95.36 59.2 0 top
NOREF#11  -  []  14.51 163.34 0 top
NOREF#12  -  [unnamed#3]  17.43 10.68 0 top
NOREF#13  -  [unnamed#3]  129.57 83.07 0 top
NOREF#14  -  [unnamed#2]  12.64 87.99 180 top
NOREF#15  -  []  -89.59 -155.68 0 top
NOREF#16  -  []  0.16 10.05 0 top
NOREF#17  -  [unnamed#4]  50.24 50.05 90 top
NOREF#18  -  [unnamed#4]  50.24 77.99 90 top
NOREF#19  -  [unnamed#2]  72.08 87.99 180 top
NOREF#20  -  []  51.26 10.05 0 top
NOREF#21  -  [unnamed#4]  50.24 17.03 90 top
NOREF#22  -  [unnamed#2]  155.65 87.99 180 top
NOREF#23  -  [unnamed#2]  152.6 6 0 top
NOREF#24  -  []  3.46 7 90 top
NOREF#25  -  []  -141.22 32.37 0 top
NOREF#26  -  []  55.53 66.69 0 top
NOREF#27  -  [unnamed#3]  21.6 82.84 0 top
NOREF#28  -  [unnamed#2]  111.45 87.99 180 top
NOREF#29  -  []  31.27 211.09 0 top
NOREF#30  -  [unnamed#2]  107.77 6 0 top
NOREF#31  -  [unnamed#3]  17.43 10.68 180 bottom
NOREF#32  -  [unnamed#3]  21.6 82.84 180 bottom
NOREF#33  -  [unnamed#3]  129.57 83.07 180 bottom
OSC1  25MHZ  [HSX4-0503]  130.08 66.82 0 top
Q1  PMOS-GSD  [SOT23]  140.11 29.73 270 top
Q2  PMOS-GSD  [SOT23]  139.86 32.4 90 bottom
Q3  NPN-BEC  [SOT23]  139.35 24.53 90 top
Q4  NPN-BEC  [SOT23]  137.32 37.61 0 bottom
Q5  NPN-BEC  [SOT23]  83.22 79.14 180 bottom
Q6  NPN-BEC  [SOT23]  33.3 68.98 0 top
R1  100/NC  [SR0603]  83.34 76.34 0 bottom
R2  100  [SR0603]  87.15 82.49 270 bottom
R3  47K  [SR0402]  19.59 37.09 90 top
R4  510  [SR0603]  132.49 63.26 0 top
R5  510  [SR0603]  142.65 61.61 0 bottom
R6  27K  [SR0603]  144.56 47.51 180 top
R7  100  [SR0402]  79.28 73.42 0 top
R8  33  [SR0402]  95.79 62.75 270 top
R9  100  [SR0402]  137.06 25.92 180 top
R10  100  [SR0402]  136.81 34.3 180 bottom
R11  30.1K  [SR0603]  111.92 52.72 90 top
R12  30.1K  [SR0603]  106.71 46.75 180 bottom
R13  30.1K  [SR0603]  96.8 24.78 0 bottom
R14  604K  [SR0603]  91.45 15.59 0 top
R15  2.2K  [SR0402]  20.6 37.09 90 top
R16  5.1K  [SR0603]  17.18 24.14 90 top
R17  5.1K  [SR0603]  17.18 38.62 90 top
R18  120  [SR0402]  16.79 80.2 90 top
R19  33  [SR0402]  95.28 60.85 270 top
R20  33  [SR0402]  96.3 60.85 270 top
R21  33  [SR0402]  94.52 57.67 225 bottom
R22  33  [SR0402]  82.83 42.56 90 bottom
R23  33  [SR0402]  83.85 42.56 90 bottom
R24  33  [SR0402]  81.69 42.56 90 bottom
R25  33  [SR0402]  96.8 62.75 270 top
R26  33  [SR0402]  101.25 48.27 0 top
R27  33  [SR0402]  95.79 50.43 0 bottom
R28  33  [SR0402]  131.35 73.02 90 top
R29  1MEG  [SR0402]  74.71 48.91 270 top
R30  1MEG  [SR0402]  72.42 79.69 270 bottom
R31  150K  [SR0603]  63.91 66.46 270 bottom
R32  10  [SR0402]  79.91 77.87 180 bottom
R33  270  [SR0603]  97.06 53.51 270 bottom
R34  270  [SR0603]  95.41 53.51 270 bottom
R35  0  [SR0402]  144.05 56.53 90 top
R36  0  [SR0402]  136.7 43.96 90 top
R37  0  [SR0402]  139.22 43.96 270 top
R38  0  [SR0402]  142.4 44.46 270 top
R39  0  [SR0402]  145.19 56.53 90 top
R40  15K  [SR0402]  83.85 84.47 270 bottom
R41  10K  [SR0603]  111.16 10.94 0 top
R42  1K  [SR0402]  95.06 84.47 270 top
R43  1K  [SR0402]  79.66 42.56 90 bottom
R44  1K  [SR0402]  98.81 84.47 270 top
R45  1K  [SR0402]  96.31 84.47 270 top
R46  1K  [SR0402]  97.56 84.47 270 top
R47  1K  [SR0402]  88.07 84.47 270 top
R48  1K  [SR0402]  89.32 84.47 270 top
R49  1K  [SR0402]  90.57 84.47 270 top
R50  1K  [SR0402]  91.82 84.47 270 top
R51  1K  [SR0402]  77.75 43.7 0 bottom
R52  1K  [SR0402]  139.1 60.34 90 top
R53  1K  [SR0402]  140.11 60.34 90 top
R54  1K  [SR0402]  142.14 23.92 270 top
R55  1K  [SR0402]  143.29 23.92 270 top
R56  1K  [SR0402]  133.51 38.34 90 bottom
R57  1K  [SR0402]  134.65 38.34 90 bottom
R58  1K  [SR0402]  20.1 28.21 90 bottom
R59  1K  [SR0402]  33.36 64.53 180 top
R60  10K  [SR0402]  98.81 75.07 90 bottom
R61  10K  [SR0402]  97.56 75.07 90 bottom
R62  10K  [SR0402]  96.31 75.07 90 bottom
R63  10K  [SR0402]  95.06 75.07 90 bottom
R64  10K  [SR0402]  88.07 75.07 90 bottom
R65  10K  [SR0402]  89.32 75.07 90 bottom
R66  10K  [SR0402]  90.57 75.07 90 bottom
R67  10K  [SR0402]  91.82 75.07 90 bottom
R68  10K  [SR0402]  146.97 41.92 90 top
R69  100K  [SR0402]  22.89 45.61 270 bottom
R70  10K  [SR0402]  143.16 28.84 270 top
R71  10K  [SR0402]  142.91 33.03 90 bottom
R72  100K  [SR0402]  125.28 22.34 0 bottom
R73  100K  [SR0402]  113.06 16.65 90 bottom
R74  100K  [SR0402]  111.41 14.62 270 bottom
R75  100K  [SR0402]  125.25 23.38 180 bottom
R76  75  [SR0402]  70.39 79.69 90 bottom
R77  10  [SR0603]  33.18 73.04 90 top
R78  2.7K  [SR0402]  83.85 82.16 90 bottom
R79  2.7K  [SR0402]  82.83 82.16 90 bottom
R80  11.3K  [SR0603]  124.47 20.89 180 bottom
R81  11.3K  [SR0603]  114.2 16.52 270 top
R82  61.9K  [SR0402]  106.46 27.07 180 bottom
R83  61.9K  [SR0402]  109 52.28 180 top
R84  61.9K  [SR0402]  109 50.5 180 top
R85  61.9K  [SR0402]  94.96 21.73 270 bottom
R86  61.9K  [SR0402]  93.3 21.73 270 bottom
R87  4.7K  [SR0603]  90.94 59.58 90 bottom
R88  33  [SR0402]  97.31 60.85 270 top
R89  4.7K/NC  [SR0402]  61.88 23.66 0 top
R90  33  [SR0402]  93.25 58.43 225 bottom
R91  0/NC  [SR0603]  96.46 38.75 0 top
R92  4.7K  [SR0402]  94.14 49.44 0 bottom
R93  10K  [SR0402]  78.64 47 180 top
R94  4.7K  [SR0402]  101.25 53.35 0 top
R95  0  [SR0603]  103.79 43.45 0 top
R97  22  [SR0402]  70.39 82.49 90 bottom
R98  12K  [SR0402]  96.13 37.48 180 top
R99  33K  [SR0402]  123.09 22.77 90 bottom
R100  33K  [SR0402]  113.06 12.08 270 top
R101  33K  [SR0402]  61.6 71.9 0 bottom
R102  4.7K  [SR0603]  120.05 68.34 90 bottom
R103  7.68K  [SR0603]  123.09 25.54 270 bottom
R104  2K  [SR0402]  137.06 28.21 0 top
R105  2K  [SR0402]  136.81 33.16 0 bottom
R106  470K  [SR0402]  24.58 24.78 0 top
R107  470K  [SR0402]  23.4 39.09 270 top
R108  10K  [SR0402]  72.42 82.49 270 bottom
R109  10K  [SR0402]  81.82 84.47 90 bottom
R110  10K  [SR0402]  82.83 84.47 270 bottom
R111  10K  [SR0402]  84.87 82.16 90 bottom
R112  20K  [SR0402]  22.89 48.02 90 bottom
R113  240  [SR0402]  79.15 52.34 0 top
R114  240  [SR0402]  80.24 61.36 90 top
R115  240  [SR0402]  81.31 73.67 270 bottom
R116  1.1K  [SR0603]  19.84 19.32 0 top
R117  1.1K  [SR0603]  16.29 18.59 90 top
R118  1.1K  [SR0603]  19.46 14.99 180 top
R119  1.1K  [SR0603]  16.29 15.72 270 top
R120  1.1K  [SR0603]  32.75 18.43 0 top
R121  1.1K  [SR0603]  31.27 16.91 0 top
R122  1.1K  [SR0603]  28.57 16.91 0 top
R123  1.1K  [SR0603]  26.32 16.17 90 top
R124  1.1K  [SR0603]  34.83 16.5 90 top
R125  1.1K  [SR0603]  36.86 15.76 180 top
R126  1.1K  [SR0603]  39.65 15.76 180 top
R127  1.1K  [SR0603]  41.05 17.92 270 top
R128  30.9K  [SR0603]  111.16 9.54 180 top
R129  75  [SR0603]  94.77 42.18 180 bottom
R130  75  [SR0603]  141.64 74.82 0 bottom
R131  24.3K  [SR0603]  21.49 23.4 180 top
R132  24.3K  [SR0603]  20.73 39.38 90 top
R133  560  [HSR0402-TA]  14.76 32.62 180 top
R134  560  [HSR0402-TA]  14.89 29.62 0 top
R135  4.7K  [SR0402]  77.75 42.69 0 bottom
R136  4.7K  [SR0402]  61.88 24.78 180 top
R137  4.7K  [SR0402]  70.13 19.19 90 top
R138  4.7K  [SR0402]  79.63 29.99 180 bottom
R139  4.7K  [SR0402]  71.79 32.27 0 bottom
R140  4.7K/NC  [SR0402]  62.01 30.22 180 top
R141  4.7K  [SR0402]  118.27 77.1 180 top
R142  4.7K  [SR0402]  124.13 66.69 180 top
R143  4.7K  [SR0402]  125.38 68.59 0 top
R144  4.7K  [SR0402]  115.98 73.55 0 top
R145  4.7K  [SR0402]  113.7 72.02 0 top
R146  4.7K  [SR0402]  115.98 74.56 0 top
R147  4.7K  [SR0402]  123.73 68.09 90 top
R148  4.7K  [SR0402]  115.98 75.58 0 top
R149  4.7K/NC  [SR0402]  129.21 63.9 0 top
R150  4.7K/NC  [SR0402]  142.91 56.53 90 top
R151  4.7K  [SR0402]  141.76 56.53 90 top
R152  4.7K  [SR0402]  25.05 45.23 180 top
R153  4.7K  [SR0402]  146.99 31.28 0 top
R154  4.7K  [SR0402]  146.99 32.38 0 top
R155  4.7K  [SR0402]  146.99 26.88 0 top
R156  4.7K  [SR0402]  146.99 25.78 0 top
R157  4.7K  [SR0402]  146.99 33.48 0 top
R158  4.7K  [SR0402]  146.99 24.68 0 top
R159  4.7K  [SR0402]  146.99 37.78 0 bottom
R160  4.7K  [SR0402]  146.99 28.98 0 bottom
R161  4.7K  [SR0402]  146.99 36.68 0 bottom
R162  4.7K  [SR0402]  146.99 35.58 0 bottom
R163  4.7K  [SR0402]  146.99 30.08 0 bottom
R164  4.7K  [SR0402]  146.99 31.18 0 bottom
R165  4.7K  [SR0402]  77.17 78.12 180 bottom
R166  4.7K  [SR0402]  84.87 84.47 90 bottom
R167  NC/4.7K  [SR0402]  66.83 80.36 270 bottom
R168  NC/4.7K  [SR0402]  68.51 84.85 0 bottom
R169  4.7K  [SR0402]  23.47 64.78 270 bottom
R171  200  [SR0402]  11.59 46.24 0 top
R172  51K  [SR0402]  25.43 62.05 270 top
R173  51K  [SR0402]  25.43 63.97 270 top
R174  1K  [SR0402]  78.21 61.36 270 top
R175  1K  [SR0402]  77.2 61.36 90 top
R176  1K  [SR0402]  82.83 73.8 90 top
R177  1K  [SR0402]  81.82 73.8 270 top
R178  1K  [SR0402]  79.23 61.36 90 bottom
R179  1K  [SR0402]  78.21 61.36 270 bottom
R180  1K  [SR0402]  78.26 73.67 270 bottom
R181  1K  [SR0402]  79.28 73.67 90 bottom
R182  1K  [SR0402]  77.25 80.28 0 top
R183  2K  [SR0603]  144.68 45.31 270 bottom
R184  2K  [SR0603]  146.97 45.31 270 bottom
R185  2K  [SR0603]  33.03 65.93 180 top
R186  12K  [SR0603]  108.95 29.05 270 bottom
R187  100K  [SR0603]  66.71 72.53 270 bottom
R188  0  [SR0603]  66.71 69.26 270 bottom
R189  0/NC  [SR0603]  65.31 69.26 270 bottom
R190  604  [SR0603]  111.03 29.73 0 bottom
R191  69.8K  [SR0603]  111.03 28.34 180 bottom
R192  1K  [SR0603]  109.56 32.25 0 bottom
R193  0  [SR0603]  63.91 69.26 90 bottom
R194  80.6K  [SR0603]  106.16 29.05 270 bottom
R195  120K  [SR0603]  113.7 44.08 90 bottom
R196  120K  [SR0603]  107.45 44.69 270 bottom
R197  243K  [SR0402]  107.04 49.42 0 bottom
R198  243K  [SR0402]  112.93 50.56 180 top
R199  24.3K  [SR0603]  112.3 44.08 270 bottom
R200  1K  [SR0603]  109.63 44.08 90 bottom
R201  24.3K  [SR0603]  106.08 44.69 90 bottom
R202  1K  [SR0603]  102.9 44.69 270 bottom
R203  0  [SR0603]  92.49 17.69 270 top
R204  243K  [SR0402]  94.34 23.38 180 bottom
R205  120K  [SR0603]  94.01 24.78 0 bottom
R206  24.3K  [SR0603]  94.01 26.18 180 bottom
R207  1K  [SR0603]  94.01 28.72 0 bottom
R208  0  [SR0603]  103.79 40.65 0 top
R209  0  [SR0603]  103.79 42.05 0 top
R212  0/NC  [SR0603]  79.15 27.95 90 bottom
R213  0  [SR0603]  77.75 27.95 90 bottom
R214  4.32K  [SR0603]  142.4 47 90 top
R216  0  [SR0603]  128.35 74.18 270 top
R217  0/NC  [SR0603]  129.06 73.42 180 top
R218  0  [SR0603]  129.06 71.77 180 top
R219  NC/0  [SR0603]  148.11 47.51 180 top
R220  0/NC  [SR0603]  37.52 20.13 90 top
R221  0  [SR0603]  36.78 20.84 0 top
R222  0  [SR0603]  39.6 20.84 180 top
R223  0/NC  [SR0603]  38.87 20.13 90 top
R224  0/NC  [SR0603]  26.45 26.81 270 top
R225  0/NC  [SR0603]  24.8 40.9 270 top
R226  0  [SR0603]  24.8 39.42 90 top
R227  0  [SR0603]  25.72 26.05 0 top
R228  0  [SR0603]  28.22 60.33 90 top
R229  0/NC  [SR0603]  28.22 61.81 270 top
R230  0  [SR0603]  44.23 69.23 90 top
R231  0  [SR0603]  42.7 69.23 90 top
R232  14.3K  [SR0603]  107.56 29.05 90 bottom
R233  5.6K  [SR0402]  21.65 37.09 270 top
R234  100K  [SR0402]  23.27 49.04 90 top
R235  100K  [SR0402]  77.25 81.55 180 top
R236  100K  [SR0402]  16.29 29.22 90 top
R237  100K  [SR0402]  18.45 23.81 90 top
R238  100K  [SR0402]  18.47 38.24 90 top
R239  100K  [SR0402]  16.29 33.03 270 top
R240  24.3K  [SR0603]  113.31 52.72 270 top
R241  24.3K  [SR0603]  106.71 48.15 180 bottom
R242  24.3K  [SR0603]  96.8 23.38 180 bottom
R243  2  [SR0603]  62.13 13.35 180 bottom
R244  2  [SR0603]  67.21 13.35 0 bottom
R245  301K  [SR0805]  90.71 17.88 270 top
R246  40.2K  [SR0603]  124.49 25.54 90 bottom
R247  10  [SR0402]  123.09 24.75 90 top
R248  10  [SR0402]  110.39 14.62 90 bottom
R249  10  [SR0402]  75.85 49.93 90 top
R250  6.8K  [SR0402]  71.4 82.49 90 bottom
R251  6.8K  [SR0402]  81.82 82.16 270 bottom
R252  2.49K  [SR0603]  127.67 71.01 0 bottom
R253  120K  [SR0603]  65.31 72.53 270 bottom
R500  33  [SR0402]  80.68 42.56 90 bottom
R558  4.7K/NC  [SR0603]  90.2 57.38 0 bottom
R700  33  [SR0402]  98.46 59.45 180 top
R776  33  [SR0402]  99.09 47.77 0 top
R778  33  [SR0402]  101.25 47.26 0 top
R780  33  [SR0402]  101.25 50.31 0 top
R782  33  [SR0402]  101.25 49.29 0 top
R784  33  [SR0402]  99.09 48.78 0 top
R786  33  [SR0402]  101.25 51.32 0 top
R788  33  [SR0402]  99.09 51.83 0 top
R800  33  [SR0402]  95.15 59.58 225 bottom
R801  33  [SR0402]  81.64 48.19 0 bottom
R880  33  [SR0402]  99.09 50.81 0 top
R882  33  [SR0402]  101.25 52.34 0 top
R884  33  [SR0402]  99.09 49.8 0 top
R888  100  [SR0402]  36.86 76.72 90 top
R889  100  [SR0402]  35.84 76.72 90 top
R1000  33  [SR0402]  118.27 75.07 0 top
R1001  33  [SR0402]  113.82 75.07 0 top
R1002  33  [SR0402]  118.27 73.8 0 top
R1003  33  [SR0402]  115.98 72.53 0 top
R1004  33  [SR0402]  118.27 72.4 0 top
R1005  33  [SR0402]  118.27 76.09 0 top
SW1  EMR_0415_T_V_T_R  [SW4_6M6X5M4]  96.93 78.63 0 top
SW2  EMR_0415_T_V_T_R  [SW4_6M6X5M4]  89.95 78.63 0 top
T1  G24_0413ER  [STFM24-40-280]  140.27 71 270 top
U1  TPS2553DRVR  [MLF6-065-0202L]  24.54 46.88 270 top
U2  RTL8211E_VB  [MLF48A-040-0606L]  123.16 73.37 180 top
U3  HI3519V100  [BGA389-26-2222]  88.5 50.79 270 top
U4  8PIN_SPI_FLASH  [WSON8-MX25L12835ZN]  74.71 26.84 270 top
U5  -  [SGM8903]  19.46 31.25 0 top
U6  ADM3485EAR_REEL7  [SOP8-50-150]  39.15 71.13 0 top
U7  H27U2G8F2CTR_BC  [SOP48-20-720A]  74.81 26.91 270 top
U8  PAM8303D  [MSOP8A-26-118]  23.14 62.45 0 top
U9  MP2162GQH_Z  [MLF8M-050-0202L]  63.15 71.39 0 top
U10  PI3L500ZFE  [MLF56-050-1105]  107.6 73.04 90 bottom
U11  AZ1045-04F  [DFN2510P10E_AZ1045]  148.18 52.97 270 top
U12  AZ1045-04F  [DFN2510P10E_AZ1045]  148.18 49.8 270 top
U13  SN74LVC1G125DBVR  [SOT23-5B]  93.38 30.62 270 top
U14  H5TQ4G83AFR-XXC  [BGA96-32-1609G]  80.3 67.51 180 top
U15  H5TQ4G83AFR-XXC  [BGA96-32-1609G]  80.3 67.51 180 bottom
U16  MX25L25635FMI_16PIN  [SOP16-50-300A]  74.55 26.86 180 top
U17  AZC199-04S  [SOT23-6L]  148.11 45.1 270 top
U18  MP2143  [TSOT23-8]  102.52 30.11 90 bottom
U19  TLV2372IDR  [SOP8-50-150]  77.25 82.18 90 bottom
U20  MP6507  [QFN16-050-0303LH]  64.67 15.76 0 top
U21  TPS79301  [SOT23-6B]  129.32 43.45 180 bottom
U22  SII9022  [QFN-72]  134.97 51.55 180 top
U23  MP1495S  [TSOT23-8]  111.89 15.7 180 top
U24  MP1495S  [TSOT23-8]  126.33 22.9 90 top
U25  BR_1225F1AN  [SBAT2-13A]  77.25 18.3 270 bottom
U26  MP2122  [TSOT23-8]  108.62 51.83 90 bottom
U27  MP2122  [TSOT23-8]  93.63 21.35 0 top
X1  24MEG  [HSX4-0302]  72.42 50.43 90 top
X2  32.768KHZ  [HSX2-0302]  71.83 54.76 270 top

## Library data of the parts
C1 = SC0402: signal model: DEFAULT_CAPACITOR_5.6pF_2_1
C2 C3 = SC0402: signal model: DEFAULT_CAPACITOR_20pF_2_1
C4 C217 = SC0603: signal model: DEFAULT_CAPACITOR_1000pF_2_1
C5 C127 C129-C136 C196 = SC1210B: signal model: DEFAULT_CAPACITOR_2.2e+07pF_2_1
C6 C10 = SC0805: signal model: DEFAULT_CAPACITOR_1e+07pF_2_1
C7 C8 = HSC0402-TA: signal model: DEFAULT_CAPACITOR_330000pF_2_1
C9 C267 = SC1206: signal model: DEFAULT_CAPACITOR_1e+07pF_2_1
C11 = SC0402: signal model: DEFAULT_CAPACITOR_47pF_2_1
C12 = SC0402: signal model: DEFAULT_CAPACITOR_47pF_1_2
C13 C14 C25 C26 = HSC0402: signal model: DEFAULT_CAPACITOR_2.2e+06pF_2_1
C15-C17 = SC0402: signal model: DEFAULT_CAPACITOR_2.2e+06pF_2_1
C18-C23 C176 C800 = SC0402-BGA: signal model: DEFAULT_CAPACITOR_2.2e+06pF_1_2
C24 C35-C38 C40 C54 C62 C63 C77 C78 C83 C87-C90 C97-C100 C105 C106 C235 C246 C265 C266 = SC0402: signal model: DEFAULT_CAPACITOR_100000pF_2_1
C27-C33 C128 C198-C207 = SC1206: signal model: DEFAULT_CAPACITOR_2.2e+07pF_2_1
C34 C84 C101 = SC0402
C39 C41-C46 C48 C49 C268 C269 C777 = SC0402-BGA: signal model: DEFAULT_CAPACITOR_100000pF_1_2
C47 C50-C53 C55-C61 C64-C76 C79-C82 C85 C86 C91-C96 C109 = SC0402: signal model: DEFAULT_CAPACITOR_100000pF_1_2
C110-C117 C141 C142 = SC0603: signal model: DEFAULT_CAPACITOR_100000pF_2_1
C118 = SC0402: signal model: DEFAULT_CAPACITOR_10000pF_2_1
C119-C122 C124-C126 = SC0603: signal model: DEFAULT_CAPACITOR_2.2e+06pF_2_1
C123 = SC0603
C137 C138 = SC0603: signal model: DEFAULT_CAPACITOR_15pF_2_1
C139 C140 C197 = SC0603: signal model: DEFAULT_CAPACITOR_1e+06pF_2_1
C143 = SC0402: signal model: DEFAULT_CAPACITOR_680pF_2_1
C144 = SC0402: signal model: DEFAULT_CAPACITOR_680pF_1_2
C145-C152 C175 C177 C178 = SC0402-BGA: signal model: DEFAULT_CAPACITOR_1e+06pF_1_2
C153-C159 C161-C174 C179-C183 C270 C271 = SC0402: signal model: DEFAULT_CAPACITOR_1e+06pF_2_1
C160 = SC0402: signal model: DEFAULT_CAPACITOR_1e+06pF_1_2
C184-C192 C194 C195 = SC0402: signal model: DEFAULT_CAPACITOR_4.7e+06pF_1_2
C193 = SC0402: signal model: DEFAULT_CAPACITOR_4.7e+06pF_2_1
C208 = SCAPC2-280-327: signal model: DEFAULT_CAPACITOR_2.2e+08pF_2_1
C209 = CAPC2-138-335: signal model: DEFAULT_CAPACITOR_2.2e+08pF_2_1
C210 C211 = SC0603: signal model: DEFAULT_CAPACITOR_220pF_2_1
C212-C214 = SC0402: signal model: DEFAULT_CAPACITOR_1000pF_1_2
C215 = SC0402: signal model: DEFAULT_CAPACITOR_1000pF_2_1
C216 = SC1206: signal model: DEFAULT_CAPACITOR_1000pF_2_1
C218-C221 = SC0402: signal model: DEFAULT_CAPACITOR_15pF_2_1
C222 = SC1206C: signal model: DEFAULT_CAPACITOR_1e+07pF_2_1
C223-C234 C236-C245 C247-C250 = SC0603: signal model: DEFAULT_CAPACITOR_1e+07pF_2_1
C251-C254 = SC0402: signal model: DEFAULT_CAPACITOR_33pF_1_2
C255 C256 = SC0603: signal model: DEFAULT_CAPACITOR_4.7e+06pF_2_1
C257-C260 = SC0402: signal model: DEFAULT_CAPACITOR_10pF_1_2
C261 = SC0402-BGA: signal model: DEFAULT_CAPACITOR_470000pF_1_2
C262-C264 = SC1210: signal model: DEFAULT_CAPACITOR_1e+08pF_2_1
C801 = SC0402-BGA
D1 = SD2723
D2-D14 = HSOD882
D15 = SD0805-LED
D16 = SD1714A
D17 = SD1714D
D19 D20 = HSOD323A
F1 = SF6127
J1 = SED90-F-A
J2-J5 J10 J11 = HEAD0101-T-B
J12 J13 = TF_CARD-MISOSD
J14 = USB4-200-1907
J15 = VAF2
J16 = PWC0103-M-N
J17 = J6-W2_54MM-141R
J18 = CONN80-0_8MM-ERF8-DV
J19 = CONN80-0_8MM-ERM8-DV
J20 = MJ8-SRLFY
J21 = WBC0108-49T
J22-J24 = SIP-2P
J25-J27 = WBC0104-49T
J28 = MOLEX_47151
J29 J30 = PHONEJ6
J50 = SIP-2P-20
K1 = SRLY8-87-283
L1 = SPL0404L: signal model: DEFAULT_INDUCTOR_3900nH_1_2
L2 = SL2828: signal model: DEFAULT_INDUCTOR_4700nH_2_1
L3-L10 = HSL1008: signal model: DEFAULT_INDUCTOR_2200nH_2_1
L11 = SL0805B: signal model: DEFAULT_INDUCTOR_100nH_2_1
L12 = SPL0303A: signal model: DEFAULT_INDUCTOR_4700nH_2_1
L88 = SPL0303A: signal model: DEFAULT_INDUCTOR_100nH_2_1
LB1 LB2 LB4 LB5 LB15-LB19 = SL0805
LB6-LB11 LB100 = SL0402
LB12-LB14 = SL0603
M1-M6 = MTH_C6MMD3P2MM
OSC1 = HSX4-0503
Q1-Q6 = SOT23
R1 R87 R91 R95 R189 R212 R217 R219 R220 R223 R226 R227 R229 = SR0603
R2 = SR0603: signal model: DEFAULT_RESISTOR_100OHM_2_1
R3 = SR0402: signal model: DEFAULT_RESISTOR_47000OHM_2_1
R4 R5 = SR0603: signal model: DEFAULT_RESISTOR_510OHM_2_1
R6 = SR0603: signal model: DEFAULT_RESISTOR_27000OHM_2_1
R7 R10 = SR0402: signal model: DEFAULT_RESISTOR_100OHM_1_2
R8 R19-R23 R25 R88 R90 R500 R700 R800 R801 R1000-R1005 = SR0402: signal model: DEFAULT_RESISTOR_33OHM_2_1
R9 R888 R889 = SR0402: signal model: DEFAULT_RESISTOR_100OHM_2_1
R11-R14 = SR0603: signal model: DEFAULT_RESISTOR_604000OHM_2_1
R15 = SR0402: signal model: DEFAULT_RESISTOR_2200OHM_1_2
R16 R17 = SR0603: signal model: DEFAULT_RESISTOR_5100OHM_2_1
R18 = SR0402: signal model: DEFAULT_RESISTOR_120OHM_1_2
R24 R28 = SR0402: signal model: DEFAULT_RESISTOR_33OHM_1_2
R26 R27 R71 R89 R92-R94 R140 R149 R150 R153-R164 R167 R168 R776 R778 R780 R782 R784 R786 R788 R880 R882 R884 = SR0402
R29 R30 = SR0402: signal model: DEFAULT_RESISTOR_1e+06OHM_1_2
R31 = SR0603: signal model: DEFAULT_RESISTOR_150000OHM_2_1
R32 = SR0402: signal model: DEFAULT_RESISTOR_10OHM_1_2
R33 R34 = SR0603: signal model: DEFAULT_RESISTOR_270OHM_2_1
R35 R36 R197 R198 R204 = SR0402: signal model: DEFAULT_RESISTOR_0.001OHM_2_1
R37-R39 = SR0402: signal model: DEFAULT_RESISTOR_0.001OHM_1_2
R40 = SR0402: signal model: DEFAULT_RESISTOR_15000OHM_1_2
R41 = SR0603: signal model: DEFAULT_RESISTOR_10000OHM_2_1
R42-R49 R51 R174-R177 R179 R180 = SR0402: signal model: DEFAULT_RESISTOR_1000OHM_1_2
R50 R52-R59 R178 R181 R182 = SR0402: signal model: DEFAULT_RESISTOR_1000OHM_2_1
R60-R68 = SR0402: signal model: DEFAULT_RESISTOR_10000OHM_1_2
R69 R74 R75 R235-R239 = SR0402: signal model: DEFAULT_RESISTOR_100000OHM_2_1
R70 R108-R111 = SR0402: signal model: DEFAULT_RESISTOR_10000OHM_2_1
R72 R73 R234 = SR0402: signal model: DEFAULT_RESISTOR_100000OHM_1_2
R76 = SR0402: signal model: DEFAULT_RESISTOR_75OHM_1_2
R77 = SR0603: signal model: DEFAULT_RESISTOR_10OHM_2_1
R78 = SR0402: signal model: DEFAULT_RESISTOR_2700OHM_2_1
R79 = SR0402: signal model: DEFAULT_RESISTOR_2700OHM_1_2
R80 R81 = SR0603: signal model: DEFAULT_RESISTOR_11300OHM_2_1
R82-R86 = SR0402: signal model: DEFAULT_RESISTOR_61900OHM_1_2
R97 = SR0402: signal model: DEFAULT_RESISTOR_22OHM_1_2
R98 = SR0402: signal model: DEFAULT_RESISTOR_12000OHM_1_2
R99-R101 = SR0402: signal model: DEFAULT_RESISTOR_33000OHM_2_1
R102 R558 = SR0603: signal model: DEFAULT_RESISTOR_4700OHM_2_1
R103 = SR0603: signal model: DEFAULT_RESISTOR_7680OHM_2_1
R104 R105 = SR0402: signal model: DEFAULT_RESISTOR_2000OHM_2_1
R106 R107 = SR0402: signal model: DEFAULT_RESISTOR_470000OHM_2_1
R112 = SR0402: signal model: DEFAULT_RESISTOR_20000OHM_2_1
R113-R115 = SR0402: signal model: DEFAULT_RESISTOR_240OHM_1_2
R116-R127 = SR0603: signal model: DEFAULT_RESISTOR_1100OHM_2_1
R128 = SR0603: signal model: DEFAULT_RESISTOR_30900OHM_2_1
R129 R130 = SR0603: signal model: DEFAULT_RESISTOR_75OHM_2_1
R131 R132 R199 R201 R206 = SR0603: signal model: DEFAULT_RESISTOR_24300OHM_2_1
R133 R134 = HSR0402-TA: signal model: DEFAULT_RESISTOR_560OHM_2_1
R135-R139 R141-R143 R147 R148 R151 R169 = SR0402: signal model: DEFAULT_RESISTOR_4700OHM_1_2
R144-R146 R152 R165 R166 = SR0402: signal model: DEFAULT_RESISTOR_4700OHM_2_1
R171 = SR0402: signal model: DEFAULT_RESISTOR_200OHM_1_2
R172 R173 = SR0402: signal model: DEFAULT_RESISTOR_51000OHM_1_2
R183-R185 = SR0603: signal model: DEFAULT_RESISTOR_2000OHM_2_1
R186 R187 = SR0603: signal model: DEFAULT_RESISTOR_100000OHM_2_1
R188 R193 R194 R203 R208 R209 R213 R216 R218 R221 R222 R224 R225 R228 R230 R231 = SR0603: signal model: DEFAULT_RESISTOR_0.001OHM_2_1
R190 = SR0603: signal model: DEFAULT_RESISTOR_604OHM_2_1
R191 = SR0603: signal model: DEFAULT_RESISTOR_69800OHM_2_1
R192 R200 R202 R207 = SR0603: signal model: DEFAULT_RESISTOR_1000OHM_2_1
R195 R196 R205 R253 = SR0603: signal model: DEFAULT_RESISTOR_120000OHM_2_1
R214 = SR0603: signal model: DEFAULT_RESISTOR_4320OHM_2_1
R232 = SR0603: signal model: DEFAULT_RESISTOR_200000OHM_2_1
R233 = SR0402: signal model: DEFAULT_RESISTOR_5600OHM_2_1
R240-R242 = SR0603: signal model: DEFAULT_RESISTOR_332000OHM_2_1
R243 R244 = SR0603: signal model: DEFAULT_RESISTOR_2OHM_2_1
R245 = SR0805: signal model: DEFAULT_RESISTOR_301000OHM_2_1
R246 = SR0603: signal model: DEFAULT_RESISTOR_40200OHM_2_1
R247-R249 = SR0402: signal model: DEFAULT_RESISTOR_10OHM_2_1
R250 R251 = SR0402: signal model: DEFAULT_RESISTOR_6800OHM_2_1
R252 = SR0603: signal model: DEFAULT_RESISTOR_2490OHM_2_1
SW1 SW2 = SW4_6M6X5M4
T1 = STFM24-40-280
U1 = MLF6-065-0202L
U2 = MLF48A-040-0606L
U3 = BGA389-26-2222
U4 = WSON8-MX25L12835ZN
U5 = SGM8903
U6 U19 = SOP8-50-150
U7 = SOP48-20-720A
U8 = MSOP8A-26-118
U9 = MLF8M-050-0202L
U10 = MLF56-050-1105
U11 U12 = DFN2510P10E_AZ1045
U13 = SOT23-5B
U14 U15 = BGA96-32-1609G
U16 = SOP16-50-300A
U17 = SOT23-6L
U18 U23 U24 U26 U27 = TSOT23-8
U20 = QFN16-050-0303LH
U21 = SOT23-6B
U22 = QFN-72
U25 = SBAT2-13A
X1 = HSX4-0302
X2 = HSX2-0302

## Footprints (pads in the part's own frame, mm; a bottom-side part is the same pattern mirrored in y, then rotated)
BGA96-32-1609G
  round 0.356 smd: A1(-6,-3.2) A2(-6,-2.4) A3(-6,-1.6) A7(-6,1.6) A8(-6,2.4) A9(-6,3.2) B1(-5.2,-3.2) B2(-5.2,-2.4) B3(-5.2,-1.6) B7(-5.2,1.6) B8(-5.2,2.4) B9(-5.2,3.2) C1(-4.4,-3.2) C2(-4.4,-2.4) C3(-4.4,-1.6) C7(-4.4,1.6) C8(-4.4,2.4) C9(-4.4,3.2) D1(-3.6,-3.2) D2(-3.6,-2.4) D3(-3.6,-1.6) D7(-3.6,1.6) D8(-3.6,2.4) D9(-3.6,3.2) E1(-2.8,-3.2) E2(-2.8,-2.4) E3(-2.8,-1.6) E7(-2.8,1.6) E8(-2.8,2.4) E9(-2.8,3.2) F1(-2,-3.2) F2(-2,-2.4) F3(-2,-1.6) F7(-2,1.6) F8(-2,2.4) F9(-2,3.2) G1(-1.2,-3.2) G2(-1.2,-2.4) G3(-1.2,-1.6) G7(-1.2,1.6) G8(-1.2,2.4) G9(-1.2,3.2) H1(-0.4,-3.2) H2(-0.4,-2.4) H3(-0.4,-1.6) H7(-0.4,1.6) H8(-0.4,2.4) H9(-0.4,3.2) J1(0.4,-3.2) J2(0.4,-2.4) J3(0.4,-1.6) J7(0.4,1.6) J8(0.4,2.4) J9(0.4,3.2) K1(1.2,-3.2) K2(1.2,-2.4) K3(1.2,-1.6) K7(1.2,1.6) K8(1.2,2.4) K9(1.2,3.2) L1(2,-3.2) L2(2,-2.4) L3(2,-1.6) L7(2,1.6) L8(2,2.4) L9(2,3.2) M1(2.8,-3.2) M2(2.8,-2.4) M3(2.8,-1.6) M7(2.8,1.6) M8(2.8,2.4) M9(2.8,3.2) N1(3.6,-3.2) N2(3.6,-2.4) N3(3.6,-1.6) N7(3.6,1.6) N8(3.6,2.4) N9(3.6,3.2) P1(4.4,-3.2) P2(4.4,-2.4) P3(4.4,-1.6) P7(4.4,1.6) P8(4.4,2.4) P9(4.4,3.2) R1(5.2,-3.2) R2(5.2,-2.4) R3(5.2,-1.6) R7(5.2,1.6) R8(5.2,2.4) R9(5.2,3.2) T1(6,-3.2) T2(6,-2.4) T3(6,-1.6) T7(6,1.6) T8(6,2.4) T9(6,3.2)
BGA389-26-2222
  round 0.254 smd: A1(-6.825,-6.825) A2(-6.825,-6.175) A3(-6.825,-5.525) A4(-6.825,-4.875) A5(-6.825,-4.225) A6(-6.825,-3.575) A7(-6.825,-2.925) A8(-6.825,-2.275) A9(-6.825,-1.625) A10(-6.825,-0.975) A11(-6.825,-0.325) A12(-6.825,0.325) A13(-6.825,0.975) A14(-6.825,1.625) A15(-6.825,2.275) A16(-6.825,2.925) A17(-6.825,3.575) A18(-6.825,4.225) A19(-6.825,4.875) A20(-6.825,5.525) A21(-6.825,6.175) A22(-6.825,6.825) AA1(6.175,-6.825) AA2(6.175,-6.175) AA3(6.175,-5.525) AA4(6.175,-4.875) AA5(6.175,-4.225) AA6(6.175,-3.575) AA7(6.175,-2.925) AA8(6.175,-2.275) AA9(6.175,-1.625) AA10(6.175,-0.975) AA11(6.175,-0.325) AA12(6.175,0.325) AA13(6.175,0.975) AA14(6.175,1.625) AA15(6.175,2.275) AA16(6.175,2.925) AA17(6.175,3.575) AA18(6.175,4.225) AA19(6.175,4.875) AA20(6.175,5.525) AA21(6.175,6.175) AA22(6.175,6.825) AB1(6.825,-6.825) AB2(6.825,-6.175) AB3(6.825,-5.525) AB4(6.825,-4.875) AB5(6.825,-4.225) AB6(6.825,-3.575) AB7(6.825,-2.925) AB8(6.825,-2.275) AB9(6.825,-1.625) AB10(6.825,-0.975) AB11(6.825,-0.325) AB12(6.825,0.325) AB13(6.825,0.975) AB14(6.825,1.625) AB15(6.825,2.275) AB16(6.825,2.925) AB17(6.825,3.575) AB18(6.825,4.225) AB19(6.825,4.875) AB20(6.825,5.525) AB21(6.825,6.175) AB22(6.825,6.825) B1(-6.175,-6.825) B2(-6.175,-6.175) B3(-6.175,-5.525) B4(-6.175,-4.875) B5(-6.175,-4.225) B6(-6.175,-3.575) B7(-6.175,-2.925) B8(-6.175,-2.275) B9(-6.175,-1.625) B10(-6.175,-0.975) B11(-6.175,-0.325) B12(-6.175,0.325) B13(-6.175,0.975) B14(-6.175,1.625) B15(-6.175,2.275) B16(-6.175,2.925) B17(-6.175,3.575) B18(-6.175,4.225) B19(-6.175,4.875) B20(-6.175,5.525) B21(-6.175,6.175) B22(-6.175,6.825) C1(-5.525,-6.825) C2(-5.525,-6.175) C3(-5.525,-5.525) C4(-5.525,-4.875) C5(-5.525,-4.225) C6(-5.525,-3.575) C7(-5.525,-2.925) C8(-5.525,-2.275) C9(-5.525,-1.625) C10(-5.525,-0.975) C11(-5.525,-0.325) C12(-5.525,0.325) C13(-5.525,0.975) C14(-5.525,1.625) C15(-5.525,2.275) C16(-5.525,2.925) C17(-5.525,3.575) C18(-5.525,4.225) C19(-5.525,4.875) C20(-5.525,5.525) C21(-5.525,6.175) C22(-5.525,6.825) D1(-4.875,-6.825) D2(-4.875,-6.175) D3(-4.875,-5.525) D4(-4.875,-4.875) D5(-4.875,-4.225) D6(-4.875,-3.575) D7(-4.875,-2.925) D8(-4.875,-2.275) D9(-4.875,-1.625) D10(-4.875,-0.975) D11(-4.875,-0.325) D12(-4.875,0.325) D13(-4.875,0.975) D14(-4.875,1.625) D15(-4.875,2.275) D16(-4.875,2.925) D17(-4.875,3.575) D18(-4.875,4.225) D19(-4.875,4.875) D20(-4.875,5.525) D21(-4.875,6.175) D22(-4.875,6.825) E1(-4.225,-6.825) E2(-4.225,-6.175) E3(-4.225,-5.525) E4(-4.225,-4.875) E5(-4.225,-4.225) E6(-4.225,-3.575) E7(-4.225,-2.925) E8(-4.225,-2.275) E9(-4.225,-1.625) E10(-4.225,-0.975) E11(-4.225,-0.325) E12(-4.225,0.325) E13(-4.225,0.975) E14(-4.225,1.625) E18(-4.225,4.225) E19(-4.225,4.875) E20(-4.225,5.525) E21(-4.225,6.175) E22(-4.225,6.825) F1(-3.575,-6.825) F2(-3.575,-6.175) F3(-3.575,-5.525) F4(-3.575,-4.875) F5(-3.575,-4.225) F19(-3.575,4.875) F20(-3.575,5.525) F21(-3.575,6.175) F22(-3.575,6.825) G1(-2.925,-6.825) G2(-2.925,-6.175) G3(-2.925,-5.525) G4(-2.925,-4.875) G5(-2.925,-4.225) G18(-2.925,4.225) G19(-2.925,4.875) G20(-2.925,5.525) G21(-2.925,6.175) G22(-2.925,6.825) H1(-2.275,-6.825) H2(-2.275,-6.175) H3(-2.275,-5.525) H4(-2.275,-4.875) H5(-2.275,-4.225) H8(-2.275,-2.275) H9(-2.275,-1.625) H10(-2.275,-0.975) H11(-2.275,-0.325) H12(-2.275,0.325) H13(-2.275,0.975) H14(-2.275,1.625) H15(-2.275,2.275) H19(-2.275,4.875) H20(-2.275,5.525) H21(-2.275,6.175) H22(-2.275,6.825) J1(-1.625,-6.825) J2(-1.625,-6.175) J3(-1.625,-5.525) J4(-1.625,-4.875) J5(-1.625,-4.225) J8(-1.625,-2.275) J9(-1.625,-1.625) J10(-1.625,-0.975) J11(-1.625,-0.325) J12(-1.625,0.325) J13(-1.625,0.975) J14(-1.625,1.625) J15(-1.625,2.275) J18(-1.625,4.225) J19(-1.625,4.875) J20(-1.625,5.525) J21(-1.625,6.175) J22(-1.625,6.825) K1(-0.975,-6.825) K2(-0.975,-6.175) K3(-0.975,-5.525) K4(-0.975,-4.875) K5(-0.975,-4.225) K8(-0.975,-2.275) K9(-0.975,-1.625) K10(-0.975,-0.975) K11(-0.975,-0.325) K12(-0.975,0.325) K13(-0.975,0.975) K14(-0.975,1.625) K15(-0.975,2.275) K18(-0.975,4.225) K19(-0.975,4.875) K20(-0.975,5.525) K21(-0.975,6.175) K22(-0.975,6.825) L1(-0.325,-6.825) L2(-0.325,-6.175) L3(-0.325,-5.525) L4(-0.325,-4.875) L5(-0.325,-4.225) L8(-0.325,-2.275) L9(-0.325,-1.625) L10(-0.325,-0.975) L11(-0.325,-0.325) L12(-0.325,0.325) L13(-0.325,0.975) L14(-0.325,1.625) L15(-0.325,2.275) L19(-0.325,4.875) L20(-0.325,5.525) L21(-0.325,6.175) L22(-0.325,6.825) M1(0.325,-6.825) M2(0.325,-6.175) M3(0.325,-5.525) M4(0.325,-4.875) M5(0.325,-4.225) M8(0.325,-2.275) M9(0.325,-1.625) M10(0.325,-0.975) M11(0.325,-0.325) M12(0.325,0.325) M13(0.325,0.975) M14(0.325,1.625) M15(0.325,2.275) M18(0.325,4.225) M19(0.325,4.875) M20(0.325,5.525) M21(0.325,6.175) M22(0.325,6.825) N1(0.975,-6.825) N2(0.975,-6.175) N3(0.975,-5.525) N4(0.975,-4.875) N5(0.975,-4.225) N8(0.975,-2.275) N9(0.975,-1.625) N10(0.975,-0.975) N11(0.975,-0.325) N12(0.975,0.325) N13(0.975,0.975) N14(0.975,1.625) N15(0.975,2.275) N18(0.975,4.225) N19(0.975,4.875) N20(0.975,5.525) N21(0.975,6.175) N22(0.975,6.825) P1(1.625,-6.825) P2(1.625,-6.175) P3(1.625,-5.525) P4(1.625,-4.875) P5(1.625,-4.225) P8(1.625,-2.275) P9(1.625,-1.625) P10(1.625,-0.975) P11(1.625,-0.325) P12(1.625,0.325) P13(1.625,0.975) P14(1.625,1.625) P15(1.625,2.275) P19(1.625,4.875) P20(1.625,5.525) P21(1.625,6.175) P22(1.625,6.825) R1(2.275,-6.825) R2(2.275,-6.175) R3(2.275,-5.525) R4(2.275,-4.875) R5(2.275,-4.225) R8(2.275,-2.275) R9(2.275,-1.625) R10(2.275,-0.975) R11(2.275,-0.325) R12(2.275,0.325) R13(2.275,0.975) R14(2.275,1.625) R15(2.275,2.275) R19(2.275,4.875) R20(2.275,5.525) R21(2.275,6.175) R22(2.275,6.825) T1(2.925,-6.825) T2(2.925,-6.175) T3(2.925,-5.525) T4(2.925,-4.875) T5(2.925,-4.225) T18(2.925,4.225) T19(2.925,4.875) T20(2.925,5.525) T21(2.925,6.175) T22(2.925,6.825) U1(3.575,-6.825) U2(3.575,-6.175) U3(3.575,-5.525) U4(3.575,-4.875) U19(3.575,4.875) U20(3.575,5.525) U21(3.575,6.175) U22(3.575,6.825) V1(4.225,-6.825) V2(4.225,-6.175) V3(4.225,-5.525) V4(4.225,-4.875) V5(4.225,-4.225) V6(4.225,-3.575) V8(4.225,-2.275) V9(4.225,-1.625) V10(4.225,-0.975) V15(4.225,2.275) V16(4.225,2.925) V17(4.225,3.575) V18(4.225,4.225) V19(4.225,4.875) V20(4.225,5.525) V21(4.225,6.175) V22(4.225,6.825) W1(4.875,-6.825) W2(4.875,-6.175) W3(4.875,-5.525) W4(4.875,-4.875) W5(4.875,-4.225) W6(4.875,-3.575) W7(4.875,-2.925) W8(4.875,-2.275) W9(4.875,-1.625) W10(4.875,-0.975) W11(4.875,-0.325) W12(4.875,0.325) W13(4.875,0.975) W14(4.875,1.625) W15(4.875,2.275) W16(4.875,2.925) W17(4.875,3.575) W18(4.875,4.225) W19(4.875,4.875) W20(4.875,5.525) W21(4.875,6.175) W22(4.875,6.825) Y1(5.525,-6.825) Y2(5.525,-6.175) Y3(5.525,-5.525) Y4(5.525,-4.875) Y5(5.525,-4.225) Y6(5.525,-3.575) Y7(5.525,-2.925) Y8(5.525,-2.275) Y9(5.525,-1.625) Y10(5.525,-0.975) Y11(5.525,-0.325) Y12(5.525,0.325) Y13(5.525,0.975) Y14(5.525,1.625) Y15(5.525,2.275) Y16(5.525,2.925) Y17(5.525,3.575) Y18(5.525,4.225) Y19(5.525,4.875) Y20(5.525,5.525) Y21(5.525,6.175) Y22(5.525,6.825)
